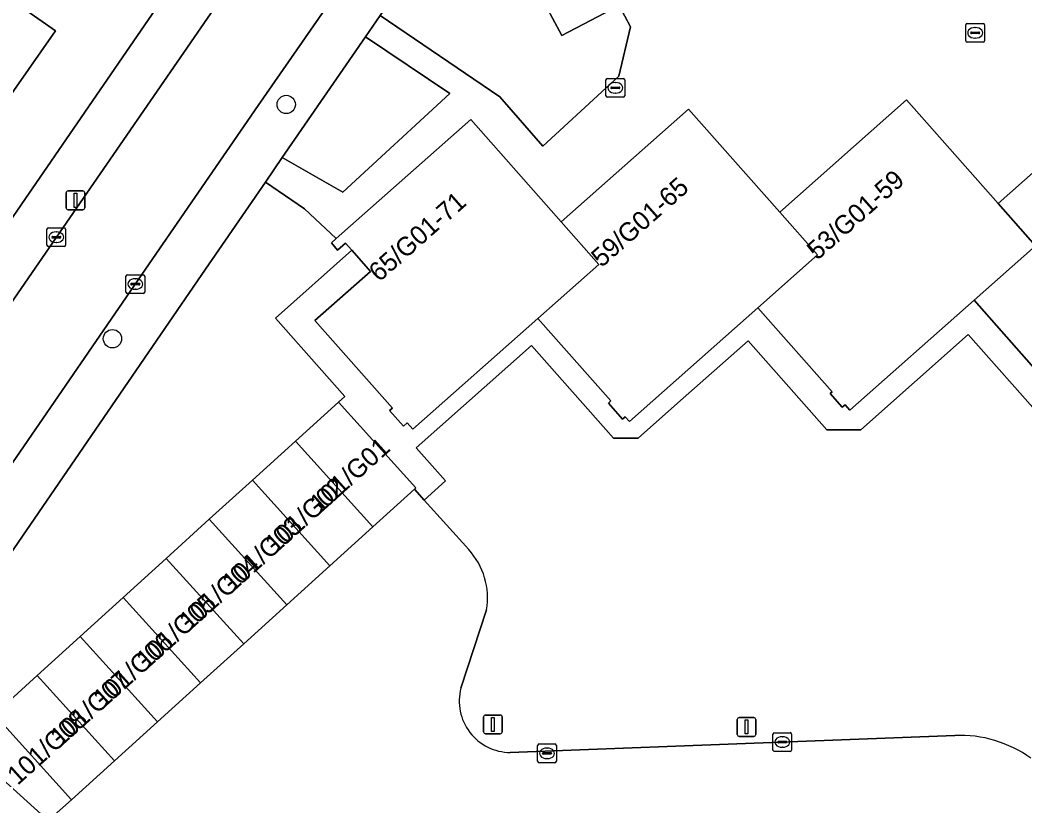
# Model space of a CAD drawing. Extents: x 160349 to 161355, y 381727 to 382854.
# Drawn here: x 160836.8 to 160890.5, y 381971.4 to 382013.3 of the extents above; entities that cross this region are included whole.
import ezdxf

# ---------------------------------------------------------------- set-up
doc = ezdxf.new("R2010")
doc.units = 0
for name, color, linetype in [('IMGEO_Boom', 7, 'Continuous'), ('IMGEO_Erf', 7, 'Continuous'), ('IMGEO_Groenvoorziening', 7, 'Continuous'), ('IMGEO_Kolk', 7, 'Continuous'), ('IMGEO_Lichtmast', 7, 'Continuous'), ('IMGEO_Pand', 7, 'Continuous'), ('IMGEO_Pand_nummerreeks', 7, 'Continuous'), ('IMGEO_Parkeervlak_open', 7, 'Continuous'), ('IMGEO_Rijbaan_lokaal_open', 7, 'Continuous'), ('IMGEO_Voetpad_halfverhard', 7, 'Continuous'), ('IMGEO_Voetpad_open', 7, 'Continuous')]:
    doc.layers.add(name, color=color, linetype=linetype)

msp = doc.modelspace()

# ---------------------------------------------------------------- linework, layer by layer
at = {"layer": 'IMGEO_Boom'}
for centre in [(160851.012, 382008.797), (160841.729, 381996.291)]:
    msp.add_circle(centre, 0.489, dxfattribs=at)
at = {"layer": 'IMGEO_Erf'}
for points in [[(160804.86, 381957.022), (160809.509, 381963.746), (160815.556, 381972.499), (160830.024, 381993.552), (160843.658, 382013.325), (160856.447, 382031.904), (160864.216, 382043.168), (160877.531, 382062.485), (160882.102, 382069.151)], [(160837.021, 382013.892), (160838.679, 382012.731), (160835.001, 382007.479)]]:
    msp.add_lwpolyline(points, dxfattribs=at)
at = {"layer": 'IMGEO_Groenvoorziening'}
for points in [[(160876.819, 382030.108), (160878.78, 382040.608), (160882.622, 382044.08), (160882.494, 382044.222), (160882.171, 382043.93), (160881.914, 382044.215), (160882.326, 382044.588), (160879.4, 382047.514), (160856.025, 382013.549), (160862.42, 382009.21), (160864.718, 382006.576), (160868.779, 382010.311), (160869.404, 382012.942), (160868.801, 382014.089), (160865.741, 382012.48), (160864.478, 382014.847)], [(160830.935, 381969.72), (160834.915, 381973.622), (160838.299, 381970.579), (160839.544, 381971.672), (160835.406, 381976.24), (160837.705, 381978.322), (160840.004, 381980.404), (160842.304, 381982.486), (160844.603, 381984.568), (160846.902, 381986.651), (160849.202, 381988.733), (160851.501, 381990.815), (160853.8, 381992.897), (160854.146, 381993.204), (160850.434, 381997.396), (160854.518, 382001.011), (160854.176, 382001.397), (160853.757, 382001.026), (160853.423, 382001.405), (160853.684, 382001.636), (160851.989, 382003.226), (160849.898, 382004.648), (160846.705, 382000), (160826.232, 381970.197)], [(160891.46, 381991.995), (160887.454, 381996.521), (160881.709, 381991.436), (160879.901, 381991.436), (160875.697, 381996.188), (160871.918, 381992.844), (160869.823, 381990.99), (160868.489, 381990.99), (160864.123, 381995.923), (160857.956, 381990.466), (160859.518, 381988.701), (160858.381, 381987.677), (160860.766, 381985.033)], [(160861.708, 381981.814), (160860.346, 381977.644)], [(160862.985, 381974.206), (160886.731, 381975.114)]]:
    msp.add_lwpolyline(points, dxfattribs=at)
msp.add_lwpolyline([(160850.803, 382005.961), (160854.038, 382004.118), (160859.749, 382009.38), (160855.241, 382012.41)], close=True, dxfattribs=at)
for centre, radius, start, end in [((160857.97, 381982.467), 3.795, 350.0849, 42.538), ((160862.993, 381976.944), 2.738, 165.1885, 269.831), ((160886.998, 381968.582), 6.537, 54.4049, 92.3412)]:
    msp.add_arc(centre, radius, start, end, dxfattribs=at)
at = {"layer": 'IMGEO_Kolk'}
for p, q in [((160887.32, 382012.196), (160887.32, 382013.048)), ((160887.395, 382013.122), (160888.247, 382013.122)), ((160887.808, 382012.902), (160887.833, 382012.902)), ((160888.321, 382013.048), (160888.321, 382012.196)), ((160887.579, 382012.616), (160887.579, 382012.628)), ((160888.017, 382012.579), (160887.619, 382012.579)), ((160887.622, 382012.665), (160888.02, 382012.665)), ((160887.831, 382012.342), (160887.806, 382012.342)), ((160888.063, 382012.628), (160888.063, 382012.616)), ((160888.247, 382012.122), (160887.395, 382012.122)), ((160868.171, 382010.186), (160869.023, 382010.186)), ((160868.096, 382009.26), (160868.096, 382010.112)), ((160868.355, 382009.68), (160868.355, 382009.692)), ((160868.793, 382009.643), (160868.395, 382009.643)), ((160868.398, 382009.729), (160868.796, 382009.729)), ((160868.584, 382009.966), (160868.609, 382009.966)), ((160868.839, 382009.692), (160868.839, 382009.68)), ((160869.097, 382010.112), (160869.097, 382009.26)), ((160869.023, 382009.186), (160868.171, 382009.186)), ((160868.607, 382009.406), (160868.582, 382009.406)), ((160838.227, 382001.285), (160838.227, 382002.137)), ((160838.302, 382002.211), (160839.154, 382002.211)), ((160839.228, 382002.137), (160839.228, 382001.285)), ((160838.486, 382001.705), (160838.486, 382001.717)), ((160838.924, 382001.668), (160838.526, 382001.668)), ((160838.529, 382001.754), (160838.927, 382001.754)), ((160838.715, 382001.991), (160838.74, 382001.991)), ((160838.97, 382001.717), (160838.97, 382001.705)), ((160839.154, 382001.211), (160838.302, 382001.211)), ((160838.738, 382001.431), (160838.713, 382001.431)), ((160842.449, 381998.785), (160842.449, 381999.637)), ((160842.524, 381999.711), (160843.376, 381999.711)), ((160842.937, 381999.491), (160842.962, 381999.491)), ((160843.45, 381999.637), (160843.45, 381998.785)), ((160842.708, 381999.205), (160842.708, 381999.217)), ((160843.146, 381999.168), (160842.748, 381999.168)), ((160842.751, 381999.254), (160843.149, 381999.254)), ((160842.96, 381998.931), (160842.935, 381998.931)), ((160843.192, 381999.217), (160843.192, 381999.205)), ((160843.376, 381998.711), (160842.524, 381998.711)), ((160877.015, 381974.336), (160877.015, 381975.188)), ((160877.09, 381975.262), (160877.942, 381975.262)), ((160877.274, 381974.756), (160877.274, 381974.768)), ((160877.317, 381974.805), (160877.715, 381974.805)), ((160877.503, 381975.042), (160877.528, 381975.042)), ((160877.758, 381974.768), (160877.758, 381974.756)), ((160878.016, 381975.188), (160878.016, 381974.336)), ((160864.445, 381973.732), (160864.445, 381974.584)), ((160864.52, 381974.658), (160865.372, 381974.658)), ((160864.933, 381974.438), (160864.958, 381974.438)), ((160865.446, 381974.584), (160865.446, 381973.732)), ((160877.942, 381974.262), (160877.09, 381974.262)), ((160877.712, 381974.719), (160877.314, 381974.719)), ((160877.526, 381974.482), (160877.501, 381974.482)), ((160864.704, 381974.152), (160864.704, 381974.164)), ((160865.142, 381974.115), (160864.744, 381974.115)), ((160864.747, 381974.201), (160865.145, 381974.201)), ((160864.956, 381973.878), (160864.931, 381973.878)), ((160865.188, 381974.164), (160865.188, 381974.152)), ((160865.372, 381973.658), (160864.52, 381973.658))]:
    msp.add_line(p, q, dxfattribs=at)
for points in [[(160887.32, 382012.196), (160887.32, 382013.048)], [(160887.395, 382013.122), (160888.247, 382013.122)], [(160888.321, 382013.048), (160888.321, 382012.196)], [(160888.247, 382012.122), (160887.395, 382012.122)], [(160868.171, 382010.186), (160869.023, 382010.186)], [(160868.096, 382009.26), (160868.096, 382010.112)], [(160869.097, 382010.112), (160869.097, 382009.26)], [(160869.023, 382009.186), (160868.171, 382009.186)], [(160838.227, 382001.285), (160838.227, 382002.137)], [(160838.302, 382002.211), (160839.154, 382002.211)], [(160839.228, 382002.137), (160839.228, 382001.285)], [(160839.154, 382001.211), (160838.302, 382001.211)], [(160842.449, 381998.785), (160842.449, 381999.637)], [(160842.524, 381999.711), (160843.376, 381999.711)], [(160843.45, 381999.637), (160843.45, 381998.785)], [(160843.376, 381998.711), (160842.524, 381998.711)], [(160877.015, 381974.336), (160877.015, 381975.188)], [(160877.09, 381975.262), (160877.942, 381975.262)], [(160878.016, 381975.188), (160878.016, 381974.336)], [(160864.445, 381973.732), (160864.445, 381974.584)], [(160864.52, 381974.658), (160865.372, 381974.658)], [(160865.446, 381974.584), (160865.446, 381973.732)], [(160877.942, 381974.262), (160877.09, 381974.262)], [(160865.372, 381973.658), (160864.52, 381973.658)]]:
    msp.add_lwpolyline(points, dxfattribs=at)
for centre, radius, start, end in [((160887.397, 382013.046), 0.0765, 91.552, 178.448), ((160887.397, 382013.046), 0.0765, 91.552, 178.448), ((160888.245, 382013.046), 0.0765, 1.552, 88.448), ((160888.245, 382013.046), 0.0765, 1.552, 88.448), ((160887.619, 382012.625), 0.0403, 85.8775, 175.7526), ((160887.616, 382012.615), 0.0366, 178.938, 274.7102), ((160888.02, 382012.622), 0.043, 264.8664, 352.4533), ((160888.024, 382012.627), 0.0386, 1.7309, 96.639), ((160887.397, 382012.198), 0.0765, 181.552, 268.448), ((160887.397, 382012.198), 0.0765, 181.552, 268.448), ((160888.245, 382012.198), 0.0765, 271.552, 358.448), ((160888.245, 382012.198), 0.0765, 271.552, 358.448), ((160868.173, 382010.11), 0.0765, 91.552, 178.448), ((160868.173, 382010.11), 0.0765, 91.552, 178.448), ((160869.021, 382010.11), 0.0765, 1.552, 88.448), ((160869.021, 382010.11), 0.0765, 1.552, 88.448), ((160868.395, 382009.689), 0.0403, 85.8775, 175.7526), ((160868.392, 382009.679), 0.0366, 178.938, 274.7102), ((160868.796, 382009.686), 0.043, 264.8664, 352.4533), ((160868.8, 382009.691), 0.0386, 1.7309, 96.639), ((160868.173, 382009.262), 0.0765, 181.552, 268.448), ((160868.173, 382009.262), 0.0765, 181.552, 268.448), ((160869.021, 382009.262), 0.0765, 271.552, 358.448), ((160869.021, 382009.262), 0.0765, 271.552, 358.448), ((160838.304, 382002.135), 0.0765, 91.552, 178.448), ((160838.304, 382002.135), 0.0765, 91.552, 178.448), ((160839.152, 382002.135), 0.0765, 1.552, 88.448), ((160839.152, 382002.135), 0.0765, 1.552, 88.448), ((160838.526, 382001.714), 0.0403, 85.8775, 175.7526), ((160838.523, 382001.704), 0.0366, 178.938, 274.7102), ((160838.927, 382001.711), 0.043, 264.8664, 352.4533), ((160838.931, 382001.716), 0.0386, 1.7309, 96.639), ((160838.304, 382001.287), 0.0765, 181.552, 268.448), ((160838.304, 382001.287), 0.0765, 181.552, 268.448), ((160839.152, 382001.287), 0.0765, 271.552, 358.448), ((160839.152, 382001.287), 0.0765, 271.552, 358.448), ((160842.526, 381999.635), 0.0765, 91.552, 178.448), ((160842.526, 381999.635), 0.0765, 91.552, 178.448), ((160843.374, 381999.635), 0.0765, 1.552, 88.448), ((160843.374, 381999.635), 0.0765, 1.552, 88.448), ((160842.748, 381999.214), 0.0403, 85.8775, 175.7526), ((160842.745, 381999.204), 0.0366, 178.938, 274.7102), ((160843.149, 381999.211), 0.043, 264.8664, 352.4533), ((160843.153, 381999.216), 0.0386, 1.7309, 96.639), ((160842.526, 381998.787), 0.0765, 181.552, 268.448), ((160842.526, 381998.787), 0.0765, 181.552, 268.448), ((160843.374, 381998.787), 0.0765, 271.552, 358.448), ((160843.374, 381998.787), 0.0765, 271.552, 358.448), ((160877.092, 381975.186), 0.0765, 91.552, 178.448), ((160877.092, 381975.186), 0.0765, 91.552, 178.448), ((160877.314, 381974.765), 0.0403, 85.8775, 175.7526), ((160877.311, 381974.755), 0.0366, 178.938, 274.7102), ((160877.715, 381974.762), 0.043, 264.8664, 352.4533), ((160877.719, 381974.767), 0.0386, 1.7309, 96.639), ((160877.94, 381975.186), 0.0765, 1.552, 88.448), ((160877.94, 381975.186), 0.0765, 1.552, 88.448), ((160864.522, 381974.582), 0.0765, 91.552, 178.448), ((160864.522, 381974.582), 0.0765, 91.552, 178.448), ((160865.37, 381974.582), 0.0765, 1.552, 88.448), ((160865.37, 381974.582), 0.0765, 1.552, 88.448), ((160877.092, 381974.338), 0.0765, 181.552, 268.448), ((160877.092, 381974.338), 0.0765, 181.552, 268.448), ((160877.94, 381974.338), 0.0765, 271.552, 358.448), ((160877.94, 381974.338), 0.0765, 271.552, 358.448), ((160864.522, 381973.734), 0.0765, 181.552, 268.448), ((160864.522, 381973.734), 0.0765, 181.552, 268.448), ((160864.744, 381974.161), 0.0403, 85.8775, 175.7526), ((160864.741, 381974.151), 0.0366, 178.938, 274.7102), ((160865.145, 381974.158), 0.043, 264.8664, 352.4533), ((160865.149, 381974.163), 0.0386, 1.7309, 96.639), ((160865.37, 381973.734), 0.0765, 271.552, 358.448), ((160865.37, 381973.734), 0.0765, 271.552, 358.448)]:
    msp.add_arc(centre, radius, start, end, dxfattribs=at)
for centre, major_axis, ratio, start_param, end_param in [((160887.807, 382012.622), (-0.387, 0.002), 0.722429, 4.712389, 7.853982), ((160887.832, 382012.622), (-0.39, 0.002), 0.717154, 1.570796, 4.712389), ((160868.583, 382009.686), (-0.387, 0.002), 0.722429, 4.712389, 7.853982), ((160868.608, 382009.686), (-0.39, 0.002), 0.717154, 1.570796, 4.712389), ((160838.714, 382001.711), (-0.387, 0.002), 0.722429, 4.712389, 7.853982), ((160838.739, 382001.711), (-0.39, 0.002), 0.717154, 1.570796, 4.712389), ((160842.936, 381999.211), (-0.387, 0.002), 0.722429, 4.712389, 7.853982), ((160842.961, 381999.211), (-0.39, 0.002), 0.717154, 1.570796, 4.712389), ((160877.502, 381974.762), (-0.387, 0.002), 0.722429, 4.712389, 7.853982), ((160877.527, 381974.762), (-0.39, 0.002), 0.717154, 1.570796, 4.712389), ((160864.932, 381974.158), (-0.387, 0.002), 0.722429, 4.712389, 7.853982), ((160864.957, 381974.158), (-0.39, 0.002), 0.717154, 1.570796, 4.712389)]:
    msp.add_ellipse(centre, major_axis=major_axis, ratio=ratio, start_param=start_param, end_param=end_param, dxfattribs=at)
at = {"layer": 'IMGEO_Lichtmast'}
for p, q in [((160839.255, 382003.28), (160839.255, 382004.08)), ((160839.255, 382004.08), (160839.255, 382003.28)), ((160839.355, 382004.18), (160840.145, 382004.18)), ((160840.145, 382004.18), (160839.355, 382004.18)), ((160840.245, 382004.08), (160840.245, 382003.28)), ((160840.245, 382003.28), (160840.245, 382004.08)), ((160840.145, 382003.18), (160839.355, 382003.18)), ((160839.355, 382003.18), (160840.145, 382003.18)), ((160861.561, 381975.302), (160861.561, 381976.102)), ((160861.561, 381976.102), (160861.561, 381975.302)), ((160861.661, 381976.202), (160862.451, 381976.202)), ((160862.451, 381976.202), (160861.661, 381976.202)), ((160862.551, 381976.102), (160862.551, 381975.302)), ((160862.551, 381975.302), (160862.551, 381976.102)), ((160875.11, 381975.166), (160875.11, 381975.966)), ((160875.11, 381975.966), (160875.11, 381975.166)), ((160875.21, 381976.066), (160876, 381976.066)), ((160876, 381976.066), (160875.21, 381976.066)), ((160876.1, 381975.966), (160876.1, 381975.166)), ((160876.1, 381975.166), (160876.1, 381975.966)), ((160862.451, 381975.202), (160861.661, 381975.202)), ((160861.661, 381975.202), (160862.451, 381975.202)), ((160876, 381975.066), (160875.21, 381975.066)), ((160875.21, 381975.066), (160876, 381975.066))]:
    msp.add_line(p, q, dxfattribs=at)
for points in [[(160839.675, 382004.055), (160839.825, 382004.055), (160839.825, 382003.305), (160839.675, 382003.305), (160839.675, 382004.055)], [(160861.981, 381976.077), (160862.131, 381976.077), (160862.131, 381975.327), (160861.981, 381975.327), (160861.981, 381976.077)], [(160875.53, 381975.941), (160875.68, 381975.941), (160875.68, 381975.191), (160875.53, 381975.191), (160875.53, 381975.941)]]:
    msp.add_lwpolyline(points, dxfattribs=at)
for centre, start, end in [((160839.355, 382004.08), 90, 180), ((160839.355, 382004.08), 90, 180), ((160840.145, 382004.08), 0, 90), ((160840.145, 382004.08), 360, 90), ((160839.355, 382003.28), 180, 270), ((160839.355, 382003.28), 180, 270), ((160840.145, 382003.28), 270, 0), ((160840.145, 382003.28), 270, 0), ((160861.661, 381976.102), 90, 180), ((160861.661, 381976.102), 90, 180), ((160862.451, 381976.102), 0, 90), ((160862.451, 381976.102), 360, 90), ((160875.21, 381975.966), 90, 180), ((160875.21, 381975.966), 90, 180), ((160876, 381975.966), 0, 90), ((160876, 381975.966), 360, 90), ((160861.661, 381975.302), 180, 270), ((160861.661, 381975.302), 180, 270), ((160862.451, 381975.302), 270, 0), ((160862.451, 381975.302), 270, 0), ((160875.21, 381975.166), 180, 270), ((160875.21, 381975.166), 180, 270), ((160876, 381975.166), 270, 0), ((160876, 381975.166), 270, 0)]:
    msp.add_arc(centre, 0.1, start, end, dxfattribs=at)
at = {"layer": 'IMGEO_Pand'}
for points in [[(160827.817, 382012.453), (160835.001, 382007.479), (160838.679, 382012.731), (160837.021, 382013.892), (160838.803, 382016.475), (160830.746, 382022.033), (160830.439, 382022.245), (160827.638, 382018.2), (160830.452, 382016.259)], [(160887.764, 381998.351), (160891.758, 381993.837), (160891.622, 381993.717), (160892.301, 381992.949), (160892.453, 381993.084), (160892.734, 381992.766), (160899.542, 381998.79), (160902.708, 382001.592), (160900.733, 382003.824), (160895.757, 382009.447), (160889.052, 382003.514), (160891.049, 382001.258)], [(160887.764, 381998.351), (160891.049, 382001.258), (160889.052, 382003.514), (160884.155, 382009.049), (160877.378, 382003.052), (160879.402, 382000.764), (160876.21, 381997.94), (160880.173, 381993.461), (160880.068, 381993.368), (160880.721, 381992.631), (160880.873, 381992.766), (160881.128, 381992.478)], [(160864.454, 381997.37), (160868.35, 381992.968), (160868.225, 381992.858), (160868.979, 381992.005), (160869.117, 381992.127), (160869.347, 381991.867), (160876.21, 381997.94), (160879.402, 382000.764), (160877.378, 382003.052), (160872.511, 382008.553), (160865.703, 382002.529), (160867.715, 382000.255)], [(160867.715, 382000.255), (160865.703, 382002.529), (160860.869, 382007.993), (160853.684, 382001.636), (160853.423, 382001.405), (160853.757, 382001.026), (160854.176, 382001.397), (160854.518, 382001.011), (160855.413, 382000), (160855.511, 381999.889), (160852.549, 381997.268), (160856.688, 381992.591), (160856.539, 381992.46), (160857.273, 381991.63), (160857.47, 381991.804), (160857.775, 381991.459), (160864.454, 381997.37)], [(160851.501, 381990.815), (160855.638, 381986.246), (160857.858, 381988.257), (160857.937, 381988.328), (160853.8, 381992.897)], [(160851.501, 381990.815), (160849.202, 381988.733), (160853.339, 381984.164), (160855.638, 381986.246)], [(160846.902, 381986.651), (160851.04, 381982.082), (160853.339, 381984.164), (160849.202, 381988.733)], [(160844.603, 381984.568), (160848.74, 381980), (160851.04, 381982.082), (160846.902, 381986.651)], [(160842.304, 381982.486), (160846.441, 381977.918), (160848.74, 381980), (160844.603, 381984.568)], [(160840.004, 381980.404), (160844.142, 381975.836), (160846.441, 381977.918), (160842.304, 381982.486)], [(160837.705, 381978.322), (160841.843, 381973.753), (160844.142, 381975.836), (160840.004, 381980.404)], [(160837.705, 381978.322), (160835.406, 381976.24), (160839.544, 381971.672), (160841.843, 381973.753)]]:
    msp.add_lwpolyline(points, close=True, dxfattribs=at)
at = {"layer": 'IMGEO_Parkeervlak_open'}
msp.add_lwpolyline([(160864.478, 382014.847), (160865.741, 382012.48), (160868.801, 382014.089), (160868.345, 382014.956)], dxfattribs=at)
at = {"layer": 'IMGEO_Rijbaan_lokaal_open'}
for points in [[(160900.454, 382091.336), (160898.732, 382088.827), (160897.579, 382087.17), (160888.911, 382074.534), (160875.487, 382055.069), (160862.667, 382036.458), (160849.849, 382017.829), (160838.733, 382001.705), (160827.599, 381985.555), (160816.487, 381969.406), (160806.996, 381955.65)], [(160811.585, 381953.706), (160812.427, 381954.838), (160843.491, 382000), (160849.506, 382008.744), (160855.258, 382017.034), (160858.854, 382022.23), (160863.124, 382028.242)]]:
    msp.add_lwpolyline(points, dxfattribs=at)
at = {"layer": 'IMGEO_Voetpad_halfverhard'}
msp.add_lwpolyline([(160891.758, 381993.837), (160887.764, 381998.351), (160881.128, 381992.478), (160880.873, 381992.766), (160880.721, 381992.631), (160880.068, 381993.368), (160880.173, 381993.461), (160876.21, 381997.94), (160869.347, 381991.867), (160869.117, 381992.127), (160868.979, 381992.005), (160868.225, 381992.858), (160868.35, 381992.968), (160864.454, 381997.37), (160857.775, 381991.459), (160857.47, 381991.804), (160857.273, 381991.63), (160856.539, 381992.46), (160856.688, 381992.591), (160852.549, 381997.268), (160855.511, 381999.889), (160855.413, 382000), (160854.518, 382001.011), (160850.434, 381997.396), (160854.146, 381993.204), (160853.8, 381992.897), (160857.937, 381988.328), (160857.858, 381988.257), (160858.381, 381987.677), (160859.518, 381988.701), (160857.956, 381990.466), (160864.123, 381995.923), (160868.489, 381990.99), (160869.823, 381990.99), (160871.918, 381992.844), (160875.697, 381996.188), (160879.901, 381991.436), (160881.709, 381991.436), (160887.454, 381996.521), (160891.46, 381991.995)], dxfattribs=at)
at = {"layer": 'IMGEO_Voetpad_open'}
for points in [[(160898.701, 382093.297), (160896.288, 382089.767), (160892.908, 382084.909), (160891.222, 382082.372), (160890.681, 382081.588), (160886.418, 382075.41), (160884.468, 382072.583), (160883.88, 382071.73), (160882.102, 382069.151), (160877.531, 382062.485), (160864.216, 382043.168), (160856.447, 382031.904), (160843.658, 382013.325), (160830.024, 381993.552), (160815.556, 381972.499), (160809.509, 381963.746)], [(160905.012, 382089.324), (160903.558, 382087.228), (160902.442, 382085.568), (160894.202, 382073.493), (160889.498, 382066.61), (160885.092, 382060.107), (160882.027, 382055.784), (160877.127, 382048.557), (160873.174, 382042.828), (160871.484, 382040.355), (160867.631, 382034.676), (160864.448, 382030.182), (160863.124, 382028.242), (160858.854, 382022.23), (160855.258, 382017.034), (160849.506, 382008.744), (160843.491, 382000), (160812.427, 381954.838), (160811.585, 381953.706)], [(160816.487, 381969.406), (160827.599, 381985.555), (160838.733, 382001.705), (160849.849, 382017.829), (160862.667, 382036.458), (160875.487, 382055.069), (160888.911, 382074.534), (160897.579, 382087.17)], [(160815.016, 381954.084), (160820.18, 381961.222), (160821.136, 381962.535), (160825.506, 381968.975), (160826.232, 381970.197), (160846.705, 382000), (160849.898, 382004.648), (160850.803, 382005.961), (160855.241, 382012.41), (160856.025, 382013.549), (160879.4, 382047.514)], [(160868.345, 382014.956), (160868.801, 382014.089), (160869.404, 382012.942), (160868.779, 382010.311), (160864.718, 382006.576), (160862.42, 382009.21), (160856.025, 382013.549), (160855.241, 382012.41), (160859.749, 382009.38), (160854.038, 382004.118), (160850.803, 382005.961), (160849.898, 382004.648), (160851.989, 382003.226), (160853.684, 382001.636), (160860.869, 382007.993), (160865.703, 382002.529), (160872.511, 382008.553), (160877.378, 382003.052), (160884.155, 382009.049), (160889.052, 382003.514), (160895.757, 382009.447)], [(160860.766, 381985.033), (160858.381, 381987.677), (160857.858, 381988.257), (160855.638, 381986.246), (160853.339, 381984.164), (160851.04, 381982.082), (160848.74, 381980), (160846.441, 381977.918), (160844.142, 381975.836), (160841.843, 381973.753), (160839.544, 381971.672), (160838.299, 381970.579), (160834.915, 381973.622), (160830.935, 381969.72)], [(160860.346, 381977.644), (160861.708, 381981.814)], [(160886.731, 381975.114), (160862.985, 381974.206)]]:
    msp.add_lwpolyline(points, dxfattribs=at)
for centre, radius, start, end in [((160857.97, 381982.467), 3.795, 350.0849, 42.538), ((160862.993, 381976.944), 2.738, 165.1885, 269.831), ((160886.998, 381968.582), 6.537, 54.4049, 92.3412)]:
    msp.add_arc(centre, radius, start, end, dxfattribs=at)

# ---------------------------------------------------------------- texts
at = {"layer": 'IMGEO_Pand_nummerreeks'}
for s, rotation, p in [('59/G01-65', 41.5037, (160867.863, 382000.061)), ('53/G01-59', 41.5058, (160879.384, 382000.447)), ('65/G01-71', 41.4993, (160855.978, 381999.286)), ('101/G01', 41.9353, (160852.821, 381986.937)), ('101/G02', 41.9353, (160850.438, 381984.796)), ('101/G03', 41.9353, (160848.146, 381982.737)), ('101/G04', 41.9353, (160845.849, 381980.674)), ('101/G05', 41.9353, (160843.552, 381978.61)), ('101/G06', 41.9353, (160841.256, 381976.547)), ('101/G07', 41.9353, (160838.959, 381974.484)), ('101/G08', 41.9353, (160836.664, 381972.422))]:
    msp.add_text(s, height=1, rotation=rotation, dxfattribs=at).set_placement(p)

doc.saveas('drawing.dxf')
